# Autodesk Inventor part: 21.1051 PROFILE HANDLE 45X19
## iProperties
Created: 2007-02
Part Number: 21.1051 PROFILE HANDLE 45X19
Material: Aluminum-6061
Document SubType Name: Modeling
Designer: Andy Moles
Mass: 266.035 g
Surface Area: 816.76 cm^2
Volume: 98.1679 cm^3
Density: 2.71 g/cm^3
Description: SPECIFY LENGTH
Author: Andy Moles
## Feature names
1. Extrusion1
